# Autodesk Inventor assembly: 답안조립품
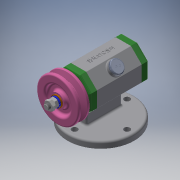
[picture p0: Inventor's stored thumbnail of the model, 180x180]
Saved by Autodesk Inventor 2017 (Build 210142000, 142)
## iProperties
Part Number: 답안조립품
Material: 일반
Document SubType Name: Assembly
Designer: mrc
Author: mrc
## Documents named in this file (14)
- C:\Users\mrc\Desktop\710204V1026\답안조립품.iam
- C:\Users\mrc\Desktop\710204V1026\본체.ipt
- C:\Users\mrc\Desktop\710204V1026\뒤커버.ipt
- C:\Users\mrc\Desktop\710204V1026\V벨트풀리.ipt
- C:\Users\mrc\Desktop\710204V1026\너트 M8.ipt
- C:\Users\mrc\Desktop\710204V1026\고무캡.ipt
- C:\Users\mrc\Desktop\710204V1026\스프링와셔 8.ipt
- C:\Users\mrc\Desktop\710204V1026\오일 실 15 25 7.ipt
- C:\Users\mrc\Desktop\710204V1026\베어링 15 x 32 x 9.ipt
- C:\Users\mrc\Desktop\710204V1026\축.ipt
- C:\Users\mrc\Desktop\710204V1026\앞커버.ipt
- C:\Users\mrc\Desktop\710204V1026\키 3 x 3 x 12.ipt
- C:\Users\mrc\Desktop\710204V1026\와셔 8x17.ipt
- C:\Users\mrc\Desktop\710204V1026\볼트 M4 x 12.ipt
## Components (2 placed, 2 different names)
1. V벨트풀리:1
2. 고무캡:1
